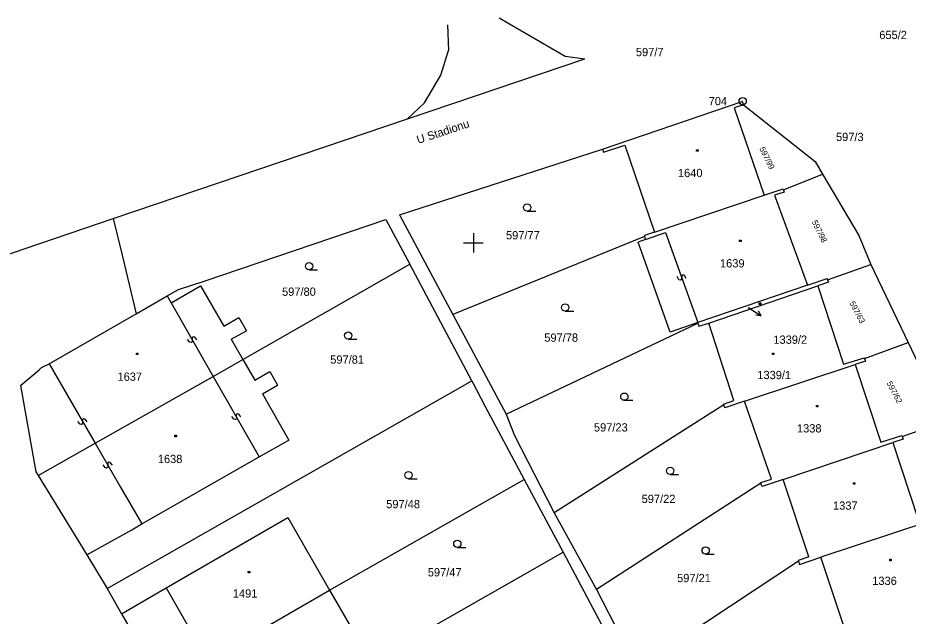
# Model space of a CAD drawing. Extents: x -493648 to -493033, y -1127718 to -1127026.
# Drawn here: x -493296.9 to -493205.2, y -1127088.4 to -1127026.8 of the extents above; entities that cross this region are included whole.
import ezdxf

# ---------------------------------------------------------------- set-up
doc = ezdxf.new("R2010")
doc.units = 0
doc.layers.add('katastrální mapa', color=7, linetype='Continuous')
doc.layers.add('síť', color=7, linetype='Continuous')

msp = doc.modelspace()

# ---------------------------------------------------------------- linework, layer by layer
at = {"layer": 'katastrální mapa'}
for p, q in [((-493247.36, -1127026.84), (-493242.01, -1127029.94)), ((-493252.66, -1127027.57), (-493252.55, -1127030.19)), ((-493253.35, -1127032.74), (-493252.55, -1127030.19)), ((-493242.01, -1127029.94), (-493240.55, -1127030.79)), ((-493256.79, -1127037.24), (-493238.51, -1127031.06)), ((-493240.55, -1127030.79), (-493238.51, -1127031.06)), ((-493255.02, -1127035.58), (-493253.35, -1127032.74)), ((-493256.79, -1127037.24), (-493255.02, -1127035.58)), ((-493222.2, -1127035.8), (-493223.15, -1127036.12)), ((-493222.2, -1127035.8), (-493214.82, -1127041.63)), ((-493223.15, -1127036.12), (-493220.06, -1127045.1)), ((-493287.07, -1127047.5), (-493256.79, -1127037.24)), ((-493257.59, -1127047.13), (-493236.71, -1127040.35)), ((-493227.02, -1127040.43), (-493226.87, -1127040.43)), ((-493227.02, -1127040.58), (-493227.02, -1127040.43)), ((-493226.87, -1127040.58), (-493227.02, -1127040.58)), ((-493226.87, -1127040.43), (-493226.87, -1127040.58)), ((-493214.82, -1127041.63), (-493214.05, -1127042.94)), ((-493218.07, -1127044.56), (-493214.05, -1127042.94)), ((-493214.05, -1127042.94), (-493210.34, -1127049.26)), ((-493231.35, -1127048.91), (-493220.06, -1127045.1)), ((-493219, -1127045.11), (-493215.62, -1127054.36)), ((-493244.46, -1127046.74), (-493243.58, -1127046.74)), ((-493300.84, -1127052.16), (-493287.07, -1127047.5)), ((-493287.07, -1127047.5), (-493286.16, -1127051.28)), ((-493277.7, -1127053.94), (-493259, -1127047.61)), ((-493259, -1127047.61), (-493256.55, -1127052.21)), ((-493257.59, -1127047.13), (-493252.12, -1127057.38)), ((-493232.37, -1127049.34), (-493252.12, -1127057.38)), ((-493232.29, -1127049.65), (-493233.05, -1127049.95)), ((-493232.37, -1127049.34), (-493232.29, -1127049.65)), ((-493222.59, -1127049.73), (-493222.44, -1127049.73)), ((-493222.59, -1127049.88), (-493222.59, -1127049.73)), ((-493222.44, -1127049.73), (-493222.44, -1127049.88)), ((-493210.34, -1127049.26), (-493209.1, -1127052.25)), ((-493229.74, -1127059.22), (-493233.05, -1127049.95)), ((-493222.44, -1127049.88), (-493222.59, -1127049.88)), ((-493286.16, -1127051.28), (-493284.71, -1127057.32)), ((-493273.73, -1127062.02), (-493256.55, -1127052.21)), ((-493250.17, -1127064.22), (-493256.55, -1127052.21)), ((-493213.54, -1127053.81), (-493209.1, -1127052.25)), ((-493209.1, -1127052.25), (-493205.26, -1127060.28)), ((-493266.91, -1127052.79), (-493266.03, -1127052.79)), ((-493228.49, -1127053.35), (-493228.55, -1127053.47)), ((-493228.39, -1127053.31), (-493228.49, -1127053.35)), ((-493228.26, -1127053.37), (-493228.39, -1127053.31)), ((-493228.1, -1127053.69), (-493228.26, -1127053.37)), ((-493280.35, -1127054.82), (-493277.7, -1127053.94)), ((-493228.86, -1127053.8), (-493229.02, -1127053.48)), ((-493228.73, -1127053.86), (-493228.86, -1127053.8)), ((-493228.63, -1127053.82), (-493228.73, -1127053.86)), ((-493228.57, -1127053.7), (-493228.63, -1127053.82)), ((-493228.55, -1127053.47), (-493228.57, -1127053.7)), ((-493215.62, -1127054.36), (-493226.9, -1127058.21)), ((-493215.62, -1127054.36), (-493213.58, -1127053.69)), ((-493213.58, -1127053.69), (-493213.54, -1127053.81)), ((-493281.51, -1127055.47), (-493280.35, -1127054.82)), ((-493281.1, -1127056.18), (-493278.07, -1127054.44)), ((-493278.07, -1127054.44), (-493275.69, -1127058.6)), ((-493225.77, -1127058.27), (-493214.54, -1127054.43)), ((-493214.54, -1127054.43), (-493211.9, -1127062.5)), ((-493284.71, -1127057.32), (-493281.51, -1127055.47)), ((-493281.51, -1127055.47), (-493281.1, -1127056.18)), ((-493281.1, -1127056.18), (-493276.77, -1127063.76)), ((-493220.57, -1127056.19), (-493220.42, -1127056.19)), ((-493220.57, -1127056.34), (-493220.57, -1127056.19)), ((-493220.42, -1127056.19), (-493220.42, -1127056.34)), ((-493240.55, -1127057.04), (-493239.67, -1127057.04)), ((-493221.7, -1127056.67), (-493221.64, -1127056.71)), ((-493221.64, -1127056.71), (-493220.37, -1127057.51)), ((-493220.37, -1127057.51), (-493220.66, -1127057.03)), ((-493220.42, -1127056.34), (-493220.57, -1127056.34)), ((-493293.66, -1127062.48), (-493284.71, -1127057.32)), ((-493275.69, -1127058.6), (-493274.13, -1127057.7)), ((-493274.13, -1127057.7), (-493273.36, -1127059.05)), ((-493252.12, -1127057.38), (-493246.64, -1127067.63)), ((-493220.37, -1127057.51), (-493220.93, -1127057.45)), ((-493246.64, -1127067.63), (-493226.88, -1127058.27)), ((-493226.9, -1127058.21), (-493229.74, -1127059.22)), ((-493226.9, -1127058.21), (-493226.88, -1127058.27)), ((-493223.18, -1127066.25), (-493225.77, -1127058.27)), ((-493278.9, -1127059.72), (-493278.94, -1127059.86)), ((-493278.94, -1127059.86), (-493278.93, -1127060.08)), ((-493278.82, -1127059.67), (-493278.9, -1127059.72)), ((-493278.68, -1127059.71), (-493278.82, -1127059.67)), ((-493278.46, -1127059.99), (-493278.68, -1127059.71)), ((-493274.92, -1127059.94), (-493273.36, -1127059.05)), ((-493279.19, -1127060.23), (-493279.41, -1127059.95)), ((-493279.05, -1127060.27), (-493279.19, -1127060.23)), ((-493278.97, -1127060.22), (-493279.05, -1127060.27)), ((-493278.93, -1127060.08), (-493278.97, -1127060.22)), ((-493274.92, -1127059.94), (-493273.73, -1127062.02)), ((-493262.88, -1127059.93), (-493262, -1127059.93)), ((-493209.73, -1127061.91), (-493205.26, -1127060.28)), ((-493205.26, -1127060.28), (-493201.38, -1127068.38)), ((-493284.68, -1127061.35), (-493284.53, -1127061.35)), ((-493284.68, -1127061.5), (-493284.68, -1127061.35)), ((-493284.53, -1127061.5), (-493284.68, -1127061.5)), ((-493284.53, -1127061.35), (-493284.53, -1127061.5)), ((-493219.22, -1127061.36), (-493219.07, -1127061.36)), ((-493219.22, -1127061.51), (-493219.22, -1127061.36)), ((-493219.07, -1127061.51), (-493219.22, -1127061.51)), ((-493219.07, -1127061.36), (-493219.07, -1127061.51)), ((-493294.46, -1127062.84), (-493293.66, -1127062.48)), ((-493293.66, -1127062.48), (-493291.51, -1127066.19)), ((-493276.77, -1127063.76), (-493273.73, -1127062.02)), ((-493273.73, -1127062.02), (-493272.51, -1127064.16)), ((-493222.08, -1127066.32), (-493210.71, -1127062.54)), ((-493210.71, -1127062.54), (-493208.06, -1127070.54)), ((-493296.62, -1127064.7), (-493294.68, -1127063.07)), ((-493294.68, -1127063.07), (-493294.46, -1127062.84)), ((-493272.51, -1127064.16), (-493270.95, -1127063.27)), ((-493270.95, -1127063.27), (-493270.16, -1127064.65)), ((-493288.94, -1127070.63), (-493276.77, -1127063.76)), ((-493287.68, -1127085.58), (-493250.17, -1127064.22)), ((-493276.77, -1127063.76), (-493272.03, -1127072.05)), ((-493250.17, -1127064.22), (-493248.78, -1127066.87)), ((-493296.62, -1127064.7), (-493295.05, -1127073.58)), ((-493271.72, -1127065.54), (-493270.16, -1127064.65)), ((-493291.51, -1127066.19), (-493288.94, -1127070.63)), ((-493271.72, -1127065.54), (-493268.99, -1127070.32)), ((-493234.46, -1127066.22), (-493233.58, -1127066.22)), ((-493248.78, -1127066.87), (-493244.77, -1127074.37)), ((-493224.22, -1127066.69), (-493241.68, -1127077.82)), ((-493219.31, -1127074.34), (-493222.08, -1127066.32)), ((-493214.68, -1127066.74), (-493214.53, -1127066.74)), ((-493214.68, -1127066.89), (-493214.68, -1127066.74)), ((-493214.53, -1127066.89), (-493214.68, -1127066.89)), ((-493214.53, -1127066.74), (-493214.53, -1127066.89)), ((-493290.11, -1127068.11), (-493290.2, -1127068.16)), ((-493289.97, -1127068.15), (-493290.11, -1127068.11)), ((-493274.65, -1127068.17), (-493274.87, -1127067.89)), ((-493274.39, -1127068.02), (-493274.43, -1127068.15)), ((-493274.37, -1127067.66), (-493274.41, -1127067.79)), ((-493274.41, -1127067.79), (-493274.39, -1127068.02)), ((-493274.28, -1127067.61), (-493274.37, -1127067.66)), ((-493274.15, -1127067.64), (-493274.28, -1127067.61)), ((-493273.93, -1127067.92), (-493274.15, -1127067.64)), ((-493246.64, -1127067.63), (-493245.78, -1127069.84)), ((-493290.48, -1127068.67), (-493290.7, -1127068.39)), ((-493290.34, -1127068.71), (-493290.48, -1127068.67)), ((-493290.25, -1127068.66), (-493290.34, -1127068.71)), ((-493290.22, -1127068.52), (-493290.25, -1127068.66)), ((-493290.2, -1127068.16), (-493290.23, -1127068.3)), ((-493290.23, -1127068.3), (-493290.22, -1127068.52)), ((-493289.75, -1127068.43), (-493289.97, -1127068.15)), ((-493274.52, -1127068.2), (-493274.65, -1127068.17)), ((-493274.43, -1127068.15), (-493274.52, -1127068.2)), ((-493205.86, -1127069.94), (-493201.38, -1127068.38)), ((-493280.72, -1127069.82), (-493280.57, -1127069.82)), ((-493280.72, -1127069.97), (-493280.72, -1127069.82)), ((-493280.57, -1127069.82), (-493280.57, -1127069.97)), ((-493245.78, -1127069.84), (-493241.68, -1127077.82)), ((-493294.81, -1127073.97), (-493288.94, -1127070.63)), ((-493288.94, -1127070.63), (-493286.33, -1127075.15)), ((-493280.57, -1127069.97), (-493280.72, -1127069.97)), ((-493272.03, -1127072.05), (-493268.99, -1127070.32)), ((-493218.11, -1127074.37), (-493206.83, -1127070.57)), ((-493287.61, -1127072.64), (-493287.64, -1127072.78)), ((-493287.52, -1127072.59), (-493287.61, -1127072.64)), ((-493287.38, -1127072.63), (-493287.52, -1127072.59)), ((-493287.16, -1127072.91), (-493287.38, -1127072.63)), ((-493284.13, -1127078.95), (-493272.03, -1127072.05)), ((-493295.05, -1127073.58), (-493294.81, -1127073.97)), ((-493287.89, -1127073.15), (-493288.11, -1127072.87)), ((-493287.75, -1127073.19), (-493287.89, -1127073.15)), ((-493287.66, -1127073.14), (-493287.75, -1127073.19)), ((-493287.63, -1127073), (-493287.66, -1127073.14)), ((-493287.64, -1127072.78), (-493287.63, -1127073)), ((-493294.81, -1127073.97), (-493289.79, -1127082.14)), ((-493264.8, -1127085.75), (-493244.77, -1127074.37)), ((-493256.68, -1127074.3), (-493255.8, -1127074.3)), ((-493244.77, -1127074.37), (-493240.77, -1127081.87)), ((-493229.75, -1127073.85), (-493228.87, -1127073.85)), ((-493218.11, -1127074.37), (-493220.28, -1127075.08)), ((-493215.46, -1127082.33), (-493218.11, -1127074.37)), ((-493286.33, -1127075.15), (-493284.13, -1127078.95)), ((-493220.4, -1127074.76), (-493237.33, -1127085.7)), ((-493220.28, -1127075.08), (-493220.4, -1127074.76)), ((-493210.87, -1127074.7), (-493210.72, -1127074.7)), ((-493210.87, -1127074.85), (-493210.87, -1127074.7)), ((-493210.72, -1127074.85), (-493210.87, -1127074.85)), ((-493210.72, -1127074.7), (-493210.72, -1127074.85)), ((-493241.68, -1127077.82), (-493237.33, -1127085.7)), ((-493285.17, -1127079.54), (-493284.13, -1127078.95)), ((-493281.62, -1127085.53), (-493269.11, -1127078.3)), ((-493269.11, -1127078.3), (-493264.8, -1127085.75)), ((-493202.95, -1127078.64), (-493214.24, -1127082.36)), ((-493289.79, -1127082.14), (-493285.17, -1127079.54)), ((-493260.55, -1127093.12), (-493240.77, -1127081.87)), ((-493251.65, -1127081.37), (-493250.77, -1127081.37)), ((-493240.77, -1127081.87), (-493236.78, -1127089.38)), ((-493289.79, -1127082.14), (-493287.68, -1127085.58)), ((-493226.09, -1127082.06), (-493225.21, -1127082.06)), ((-493211.56, -1127090.41), (-493214.24, -1127082.36)), ((-493207.13, -1127082.58), (-493206.98, -1127082.58)), ((-493207.13, -1127082.73), (-493207.13, -1127082.58)), ((-493206.98, -1127082.73), (-493207.13, -1127082.73)), ((-493206.98, -1127082.58), (-493206.98, -1127082.73)), ((-493216.54, -1127082.79), (-493233.18, -1127093.77)), ((-493273.17, -1127083.83), (-493273.02, -1127083.83)), ((-493273.17, -1127083.98), (-493273.17, -1127083.83)), ((-493273.02, -1127083.98), (-493273.17, -1127083.98)), ((-493273.02, -1127083.83), (-493273.02, -1127083.98)), ((-493286.2, -1127088.19), (-493281.62, -1127085.53)), ((-493281.62, -1127085.53), (-493277.32, -1127092.98)), ((-493287.68, -1127085.58), (-493286.2, -1127088.19)), ((-493277.32, -1127092.98), (-493264.8, -1127085.75)), ((-493264.8, -1127085.75), (-493260.55, -1127093.12)), ((-493237.33, -1127085.7), (-493233.18, -1127093.77)), ((-493286.2, -1127088.19), (-493281.98, -1127095.57))]:
    msp.add_line(p, q, dxfattribs=at)
for points in [[(-493236.71, -1127040.35), (-493222.32, -1127035.46), (-493222.2, -1127035.8)], [(-493236.71, -1127040.35), (-493236.6, -1127040.67), (-493234.41, -1127039.94), (-493231.35, -1127048.91)], [(-493220.06, -1127045.1), (-493218.1, -1127044.45), (-493218.07, -1127044.56)], [(-493218.07, -1127044.56), (-493218, -1127044.78), (-493219, -1127045.11)], [(-493231.35, -1127048.91), (-493232.39, -1127049.26), (-493232.37, -1127049.34)], [(-493232.29, -1127049.65), (-493230.22, -1127048.96), (-493226.9, -1127058.21)], [(-493213.54, -1127053.81), (-493213.45, -1127054.05), (-493214.54, -1127054.43)], [(-493226.88, -1127058.27), (-493226.78, -1127058.6), (-493225.77, -1127058.27)], [(-493211.9, -1127062.5), (-493209.75, -1127061.85), (-493209.73, -1127061.91)], [(-493209.73, -1127061.91), (-493209.65, -1127062.19), (-493210.71, -1127062.54)], [(-493224.22, -1127066.69), (-493224.24, -1127066.63), (-493223.18, -1127066.25)], [(-493222.08, -1127066.32), (-493224.13, -1127067.01), (-493224.22, -1127066.69)], [(-493208.06, -1127070.54), (-493205.89, -1127069.84), (-493205.86, -1127069.94)], [(-493205.86, -1127069.94), (-493205.76, -1127070.22), (-493206.83, -1127070.57)], [(-493206.83, -1127070.57), (-493204.19, -1127078.61), (-493202, -1127077.88)], [(-493220.4, -1127074.76), (-493220.42, -1127074.69), (-493219.31, -1127074.34)], [(-493215.46, -1127082.33), (-493216.57, -1127082.7), (-493216.54, -1127082.79)], [(-493216.54, -1127082.79), (-493216.43, -1127083.11), (-493214.24, -1127082.36)]]:
    msp.add_lwpolyline(points, dxfattribs=at)
for centre, radius in [((-493222.28, -1127035.42), 0.375), ((-493222.28, -1127035.42), 0.005), ((-493244.46, -1127046.365), 0.375), ((-493266.91, -1127052.415), 0.375), ((-493240.55, -1127056.665), 0.375), ((-493262.88, -1127059.555), 0.375), ((-493234.46, -1127065.845), 0.375), ((-493256.68, -1127073.925), 0.375), ((-493229.75, -1127073.475), 0.375), ((-493251.65, -1127080.995), 0.375), ((-493226.09, -1127081.685), 0.375)]:
    msp.add_circle(centre, radius, dxfattribs=at)
at = {"layer": 'síť'}
for p, q in [((-493250, -1127049), (-493250, -1127051)), ((-493251, -1127050), (-493249, -1127050))]:
    msp.add_line(p, q, dxfattribs=at)

# ---------------------------------------------------------------- texts
at = {"layer": 'katastrální mapa'}
for s, height, p in [('655/2', 0.849996, (-493208.22, -1127029.03)), ('597/7', 0.849996, (-493233.27, -1127030.79)), ('704', 0.849996, (-493225.78, -1127035.84)), ('597/3', 0.849996, (-493212.67, -1127039.53)), ('1640', 0.849996, (-493228.94, -1127043.24)), ('597/77', 0.849996, (-493246.64, -1127049.65)), ('1639', 0.849996, (-493224.61, -1127052.54)), ('597/80', 0.849996, (-493269.69, -1127055.46)), ('1339/2', 0.049998, (-493221.82, -1127056.67)), ('597/78', 0.849996, (-493242.7, -1127060.19)), ('1339/2', 0.849996, (-493219.12, -1127060.4)), ('597/81', 0.849996, (-493264.73, -1127062.45)), ('1637', 0.849996, (-493286.63, -1127064.21)), ('1339/1', 0.849996, (-493220.77, -1127064.04)), ('597/23', 0.849996, (-493237.59, -1127069.43)), ('1338', 0.849996, (-493216.69, -1127069.53)), ('1638', 0.849996, (-493282.48, -1127072.68)), ('597/22', 0.849996, (-493232.68, -1127076.79)), ('597/48', 0.849996, (-493258.97, -1127077.33)), ('1337', 0.849996, (-493212.98, -1127077.48)), ('597/47', 0.849996, (-493254.69, -1127084.35)), ('597/21', 0.849996, (-493229.03, -1127084.94)), ('1336', 0.849996, (-493208.94, -1127085.23)), ('1491', 0.849996, (-493274.76, -1127086.53))]:
    msp.add_text(s, height=height, dxfattribs=at).set_placement(p)
for s, height, rotation, p in [('U Stadionu', 0.849996, 18.1617278, (-493255.67, -1127039.83)), ('597/99', 0.599994, 296.28, (-493220.58, -1127040.31)), ('597/98', 0.599994, 296.28, (-493215.19, -1127047.85)), ('597/63', 0.599994, 297.765, (-493211.32, -1127056.2)), ('597/62', 0.599994, 297.765, (-493207.49, -1127064.45))]:
    msp.add_text(s, height=height, rotation=rotation, dxfattribs=at).set_placement(p)

doc.saveas('drawing.dxf')
